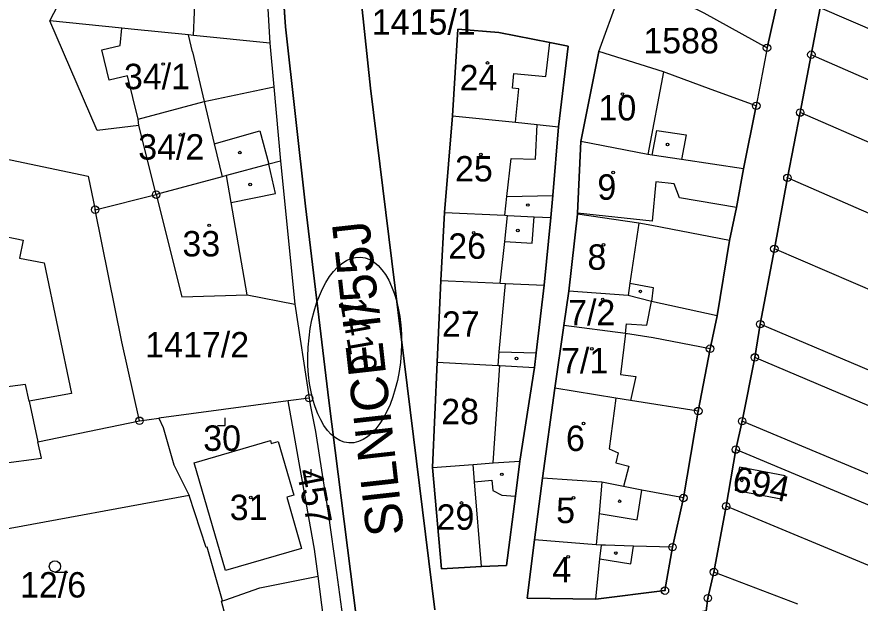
# Model space of a CAD drawing. Extents: x -537341 to -532984, y -1143469 to -1141314.
# Drawn here: x -534096.7 to -533983.8, y -1143219.6 to -1143141.1 of the extents above; entities that cross this region are included whole.
import ezdxf

# ---------------------------------------------------------------- set-up
doc = ezdxf.new("R2010")
doc.units = 0
for name, color, linetype in [('Hranice parcel', 7, 'Continuous'), ('parcelní_č_2000', 7, 'Continuous'), ('u_II_etapa', 7, 'Continuous'), ('u_obec_Horní_Moš', 7, 'Continuous'), ('u_popis', 7, 'Continuous'), ('u_ŘSD', 7, 'Continuous'), ('Vnitřní kresba', 7, 'Continuous'), ('Značky bodu BP', 7, 'Continuous'), ('Značky budov', 7, 'Continuous'), ('Značky kultur', 7, 'Continuous')]:
    doc.layers.add(name, color=color, linetype=linetype)

msp = doc.modelspace()

# ---------------------------------------------------------------- linework, layer by layer
at = {"layer": 'Hranice parcel'}
for p, q in [((-534063.52, -1143132.72), (-534062.89, -1143144.66)), ((-534018.84, -1143145.76), (-534015.29, -1143136.02)), ((-533996.31, -1143145.28), (-533994.84, -1143138.68)), ((-533989.18, -1143139.91), (-533990.38, -1143146.19)), ((-533940.79, -1143160.96), (-533989.18, -1143139.91)), ((-534062.89, -1143144.66), (-534073.09, -1143143.62)), ((-534062.89, -1143144.66), (-534062.35, -1143150.49)), ((-533996.31, -1143145.28), (-533997.75, -1143153.04)), ((-534018.84, -1143145.76), (-534021.24, -1143157.82)), ((-533990.38, -1143146.19), (-533991.87, -1143153.94)), ((-533941.88, -1143167.54), (-533990.38, -1143146.19)), ((-534062.35, -1143150.49), (-534061.42, -1143160.46)), ((-533999.48, -1143161.48), (-533997.75, -1143153.04)), ((-534038.43, -1143154.37), (-534039.5, -1143167.31)), ((-533991.87, -1143153.94), (-533993.58, -1143162.67)), ((-533941.49, -1143175.82), (-533991.87, -1143153.94)), ((-534078.08, -1143164.92), (-534080.41, -1143155.65)), ((-534021.24, -1143157.82), (-534021.67, -1143167.42)), ((-534061.42, -1143160.46), (-534059.51, -1143179.59)), ((-534000.41, -1143166.64), (-533999.48, -1143161.48)), ((-533993.58, -1143162.67), (-533995.33, -1143172.18)), ((-533941.43, -1143185.4), (-533993.58, -1143162.67)), ((-534086.26, -1143166.94), (-534078.08, -1143164.92)), ((-534001.33, -1143171.07), (-534000.41, -1143166.64)), ((-534039.5, -1143167.31), (-534039.98, -1143176.39)), ((-534026.15, -1143177.04), (-534025.25, -1143167.98)), ((-534021.68, -1143167.55), (-534022.84, -1143177.84)), ((-534021.67, -1143167.42), (-534021.68, -1143167.55)), ((-534002.98, -1143181.15), (-534001.33, -1143171.07)), ((-533995.33, -1143172.18), (-533997.21, -1143182.26)), ((-533938.53, -1143196.64), (-533995.33, -1143172.18)), ((-534039.98, -1143176.39), (-534040.45, -1143187.32)), ((-534022.84, -1143177.84), (-534023.53, -1143182.45)), ((-534059.51, -1143179.59), (-534057.6, -1143192.16)), ((-534003.94, -1143185.54), (-534002.98, -1143181.15)), ((-534023.53, -1143182.45), (-534024.73, -1143190.82)), ((-533997.21, -1143182.26), (-533997.94, -1143186.7)), ((-533912.37, -1143218.25), (-533997.21, -1143182.26)), ((-534005.51, -1143193.89), (-534003.94, -1143185.54)), ((-534040.45, -1143187.32), (-534041.08, -1143201.42)), ((-533997.94, -1143186.7), (-533999.64, -1143195.24)), ((-533899.82, -1143228.49), (-533997.94, -1143186.7)), ((-534029.39, -1143200.57), (-534027.43, -1143188.07)), ((-534024.73, -1143190.82), (-534026.35, -1143202.87)), ((-534060.41, -1143192.53), (-534077.71, -1143194.83)), ((-534057.6, -1143192.16), (-534060.41, -1143192.53)), ((-534007.5, -1143205.52), (-534005.51, -1143193.89)), ((-534080.32, -1143195.18), (-534077.71, -1143194.83)), ((-533999.64, -1143195.24), (-534000.48, -1143199.04)), ((-533879.1, -1143245.67), (-533999.64, -1143195.24)), ((-534000.48, -1143199.04), (-534001.78, -1143206.62)), ((-533869.5, -1143253.89), (-534000.48, -1143199.04)), ((-534026.35, -1143202.87), (-534027.42, -1143211.12)), ((-534073.67, -1143205.2), (-534107.09, -1143211.31)), ((-534008.96, -1143212.1), (-534007.5, -1143205.52)), ((-534001.78, -1143206.62), (-534003.42, -1143215.43)), ((-533862.31, -1143264.57), (-534001.78, -1143206.62)), ((-533992.17, -1143219.75), (-534003.42, -1143215.43)), ((-534055.69, -1143221.58), (-534056.42, -1143215.99))]:
    msp.add_line(p, q, dxfattribs=at)
for points in [[(-534061.91, -1143087.65), (-534062.34, -1143105.07), (-534062.29, -1143115.63), (-534061.93, -1143125.74), (-534060.79, -1143142.46), (-534058.08, -1143166.45), (-534054.98, -1143192.46), (-534048.78, -1143241.39), (-534046.39, -1143261.54)], [(-534040.76, -1143220.49), (-534049.39, -1143150.66), (-534051, -1143135.44), (-534051.84, -1143114.55)], [(-534092.32, -1143141.66), (-534090.18, -1143137.52), (-534086.71, -1143130.95), (-534079.93, -1143118.06)], [(-534073.09, -1143143.62), (-534072.57, -1143131.1), (-534071.45, -1143128.84)], [(-534015.29, -1143136.02), (-534006.96, -1143139.52), (-534004.77, -1143140.6), (-533996.31, -1143145.28)], [(-534073.09, -1143143.62), (-534073.76, -1143143.55), (-534081.43, -1143142.77), (-534082.69, -1143142.64), (-534092.32, -1143141.66)], [(-534080.41, -1143155.65), (-534086, -1143156.32), (-534092.32, -1143141.66)], [(-534024.21, -1143155.84), (-534022.92, -1143145.03), (-534025.38, -1143144.58), (-534032.22, -1143143.24), (-534037.69, -1143142.76), (-534038.43, -1143154.37)], [(-533997.75, -1143153.04), (-534003.77, -1143150.87), (-534010.17, -1143148.48), (-534018.84, -1143145.76)], [(-534080.41, -1143155.65), (-534080.51, -1143154.83), (-534071.65, -1143152.45), (-534062.35, -1143150.49)], [(-534038.43, -1143154.37), (-534029.96, -1143155.24), (-534027.07, -1143155.54), (-534024.21, -1143155.84)], [(-534113.97, -1143156.81), (-534087.18, -1143162.45), (-534086.26, -1143166.94)], [(-534025.25, -1143167.98), (-534025, -1143165.03), (-534024.21, -1143155.84)], [(-533999.48, -1143161.48), (-534007.76, -1143160.2), (-534011.68, -1143159.64), (-534012.28, -1143159.55), (-534021.24, -1143157.82)], [(-534061.42, -1143160.46), (-534062.99, -1143160.84), (-534068.67, -1143162.38), (-534069.26, -1143162.54), (-534078.08, -1143164.92)], [(-534078.08, -1143164.92), (-534074.66, -1143178.62), (-534065.92, -1143178.32), (-534059.51, -1143179.59)], [(-534080.32, -1143195.18), (-534082.67, -1143184.62), (-534086.26, -1143166.94)], [(-534039.5, -1143167.31), (-534031.39, -1143167.69), (-534031.05, -1143167.71), (-534027.48, -1143167.88), (-534025.25, -1143167.98)], [(-534001.33, -1143171.07), (-534011.71, -1143169.07), (-534013.46, -1143168.73), (-534021.68, -1143167.55)], [(-534039.98, -1143176.39), (-534032.04, -1143176.76), (-534031.34, -1143176.8), (-534026.15, -1143177.04)], [(-534027.43, -1143188.07), (-534027.2, -1143186.08), (-534026.15, -1143177.04)], [(-534002.98, -1143181.15), (-534011.76, -1143179.24), (-534014.91, -1143178.42), (-534022.84, -1143177.84)], [(-534003.94, -1143185.54), (-534011.53, -1143184.08), (-534015.26, -1143183.49), (-534023.53, -1143182.45)], [(-534040.45, -1143187.32), (-534032.32, -1143187.79), (-534032.07, -1143187.8), (-534027.43, -1143188.07)], [(-534005.51, -1143193.89), (-534014.59, -1143192.49), (-534016.56, -1143192.16), (-534024.73, -1143190.82)], [(-534117.77, -1143193.13), (-534105.37, -1143192.05), (-534104.3, -1143201.62), (-534093.45, -1143200.21), (-534093.95, -1143198.01), (-534080.32, -1143195.18)], [(-534056.42, -1143215.99), (-534056.89, -1143212.39), (-534057.64, -1143208.15), (-534059.61, -1143197.01), (-534060.41, -1143192.53)], [(-534057.6, -1143192.16), (-534057.46, -1143193.07), (-534056.77, -1143196.62), (-534055.08, -1143207.53), (-534053.95, -1143215.5), (-534053.13, -1143221.37)], [(-534077.71, -1143194.83), (-534077.14, -1143196.1), (-534075.7, -1143201.08), (-534073.67, -1143205.2)], [(-534059.67, -1143205.16), (-534060.6, -1143205.41), (-534058.64, -1143212.28), (-534068.82, -1143215.22), (-534072.99, -1143200.81), (-534062.78, -1143197.81), (-534062.67, -1143198.23), (-534061.74, -1143197.98), (-534059.67, -1143205.16)], [(-534041.08, -1143201.42), (-534035.64, -1143201.02), (-534032.99, -1143200.83), (-534029.39, -1143200.57)], [(-534041.08, -1143201.42), (-534039.89, -1143215.01), (-534034.52, -1143214.7), (-534031.2, -1143214.56), (-534029.99, -1143205.29), (-534029.39, -1143200.57)], [(-533994.42, -1143205.62), (-533993.88, -1143202.57), (-534000, -1143201.41), (-534000.57, -1143204.45), (-533994.42, -1143205.62)], [(-534007.5, -1143205.52), (-534013.05, -1143204.45), (-534015.52, -1143203.97), (-534018.43, -1143203.41), (-534026.35, -1143202.87)], [(-534069.19, -1143219.29), (-534071.26, -1143212.1), (-534071.41, -1143212.14), (-534073.67, -1143205.2)], [(-534027.42, -1143211.12), (-534028.44, -1143218.92), (-534019.21, -1143219.08), (-534009.98, -1143217.92), (-534008.96, -1143212.1)], [(-534008.96, -1143212.1), (-534014.17, -1143211.95), (-534017.95, -1143211.85), (-534018.49, -1143211.83), (-534019.19, -1143211.81), (-534027.42, -1143211.12)], [(-534003.42, -1143215.43), (-534004.23, -1143218.93), (-534004.45, -1143220.61), (-534008.52, -1143221.33), (-534023.43, -1143221.73), (-534023.59, -1143233.75)], [(-534069.19, -1143219.29), (-534068.9, -1143219.21), (-534064.19, -1143217.54), (-534056.42, -1143215.99)], [(-534070.76, -1143223.04), (-534068.43, -1143222.69), (-534069.33, -1143219.33), (-534069.19, -1143219.29)]]:
    msp.add_lwpolyline(points, dxfattribs=at)
at = {"layer": 'u_II_etapa'}
msp.add_ellipse((-534051.51, -1143185.72), major_axis=(-0.77, -12.43), ratio=0.50074, dxfattribs=at)
msp.add_ellipse((-534051.51, -1143185.72), major_axis=(-0.77, -12.43), ratio=0.50074, dxfattribs=at)
at = {"layer": 'u_obec_Horní_Moš'}
for p, q in [((-534063.52, -1143132.72), (-534062.89, -1143144.66)), ((-534018.84, -1143145.76), (-534015.29, -1143136.02)), ((-533994.84, -1143138.68), (-533996.31, -1143145.28)), ((-533990.38, -1143146.19), (-533989.18, -1143139.91)), ((-534058.08, -1143166.45), (-534060.79, -1143142.46)), ((-534062.89, -1143144.66), (-534062.35, -1143150.49)), ((-533996.31, -1143145.28), (-533997.75, -1143153.04)), ((-534021.24, -1143157.82), (-534018.84, -1143145.76)), ((-533991.87, -1143153.94), (-533990.38, -1143146.19)), ((-534062.35, -1143150.49), (-534061.42, -1143160.46)), ((-533997.75, -1143153.04), (-533999.48, -1143161.48)), ((-534039.5, -1143167.31), (-534038.43, -1143154.37)), ((-533993.58, -1143162.67), (-533991.87, -1143153.94)), ((-534078.08, -1143164.92), (-534080.41, -1143155.65)), ((-534021.67, -1143167.42), (-534021.24, -1143157.82)), ((-534061.42, -1143160.46), (-534059.51, -1143179.59)), ((-533999.48, -1143161.48), (-534000.41, -1143166.64)), ((-533995.33, -1143172.18), (-533993.58, -1143162.67)), ((-534086.26, -1143166.94), (-534078.08, -1143164.92)), ((-534000.41, -1143166.64), (-534001.33, -1143171.07)), ((-534039.98, -1143176.39), (-534039.5, -1143167.31)), ((-534025.25, -1143167.98), (-534026.15, -1143177.04)), ((-534022.84, -1143177.84), (-534021.68, -1143167.55)), ((-534021.68, -1143167.55), (-534021.67, -1143167.42)), ((-534001.33, -1143171.07), (-534002.98, -1143181.15)), ((-533997.21, -1143182.26), (-533995.33, -1143172.18)), ((-534040.45, -1143187.32), (-534039.98, -1143176.39)), ((-534023.53, -1143182.45), (-534022.84, -1143177.84)), ((-534059.51, -1143179.59), (-534057.6, -1143192.16)), ((-534002.98, -1143181.15), (-534003.94, -1143185.54)), ((-534024.73, -1143190.82), (-534023.53, -1143182.45)), ((-533997.94, -1143186.7), (-533997.21, -1143182.26)), ((-534003.94, -1143185.54), (-534005.51, -1143193.89)), ((-534041.08, -1143201.42), (-534040.45, -1143187.32)), ((-533999.64, -1143195.24), (-533997.94, -1143186.7)), ((-534027.43, -1143188.07), (-534029.39, -1143200.57)), ((-534026.35, -1143202.87), (-534024.73, -1143190.82)), ((-534005.51, -1143193.89), (-534007.5, -1143205.52)), ((-534000.48, -1143199.04), (-533999.64, -1143195.24)), ((-534001.78, -1143206.62), (-534000.48, -1143199.04)), ((-534029.39, -1143200.57), (-534029.99, -1143205.29)), ((-534027.42, -1143211.12), (-534026.35, -1143202.87)), ((-534007.5, -1143205.52), (-534008.96, -1143212.1)), ((-534003.42, -1143215.43), (-534001.78, -1143206.62))]:
    msp.add_line(p, q, dxfattribs=at)
for points in [[(-534051.84, -1143114.55), (-534051, -1143135.44), (-534049.39, -1143150.66), (-534040.76, -1143220.49)], [(-534060.79, -1143142.46), (-534061.93, -1143125.74), (-534062.29, -1143115.63)], [(-534092.32, -1143141.66), (-534090.18, -1143137.52), (-534086.71, -1143130.95), (-534079.93, -1143118.06)], [(-534080.41, -1143155.65), (-534086, -1143156.32), (-534092.32, -1143141.66)], [(-534038.43, -1143154.37), (-534037.69, -1143142.76), (-534032.22, -1143143.24), (-534025.38, -1143144.58), (-534022.92, -1143145.03), (-534024.21, -1143155.84)], [(-534113.97, -1143156.81), (-534087.18, -1143162.45), (-534086.26, -1143166.94)], [(-534024.21, -1143155.84), (-534025, -1143165.03), (-534025.25, -1143167.98)], [(-534048.78, -1143241.39), (-534054.98, -1143192.46), (-534058.08, -1143166.45)], [(-534026.15, -1143177.04), (-534027.2, -1143186.08), (-534027.43, -1143188.07)], [(-534057.6, -1143192.16), (-534057.46, -1143193.07), (-534056.77, -1143196.62), (-534055.08, -1143207.53), (-534053.95, -1143215.5), (-534053.13, -1143221.37)], [(-534029.99, -1143205.29), (-534031.2, -1143214.56), (-534034.52, -1143214.7), (-534039.89, -1143215.01), (-534041.08, -1143201.42)], [(-534008.96, -1143212.1), (-534009.98, -1143217.92), (-534019.21, -1143219.08), (-534028.44, -1143218.92), (-534027.42, -1143211.12)], [(-534023.59, -1143233.75), (-534023.43, -1143221.73), (-534008.52, -1143221.33), (-534004.45, -1143220.61), (-534004.23, -1143218.93), (-534003.42, -1143215.43)]]:
    msp.add_lwpolyline(points, dxfattribs=at)
at = {"layer": 'u_ŘSD'}
for p, q in [((-534061.93, -1143125.74), (-534060.79, -1143142.46)), ((-534060.79, -1143142.46), (-534058.08, -1143166.45)), ((-534058.08, -1143166.45), (-534054.98, -1143192.46)), ((-534054.98, -1143192.46), (-534048.78, -1143241.39))]:
    msp.add_line(p, q, dxfattribs=at)
msp.add_lwpolyline([(-534040.76, -1143220.49), (-534049.39, -1143150.66), (-534051, -1143135.44), (-534051.84, -1143114.55)], dxfattribs=at)
at = {"layer": 'Vnitřní kresba'}
for p, q in [((-534082.9, -1143144.95), (-534082.69, -1143142.64)), ((-534073.22, -1143145.81), (-534073.76, -1143143.55)), ((-534085.37, -1143145.54), (-534082.9, -1143144.95)), ((-534084.38, -1143149.62), (-534085.37, -1143145.54)), ((-534025.93, -1143149.09), (-534025.38, -1143144.58)), ((-534073.22, -1143145.81), (-534071.65, -1143152.45)), ((-534030.39, -1143150.67), (-534030.2, -1143148.69)), ((-534030.2, -1143148.69), (-534025.93, -1143149.09)), ((-534010.17, -1143148.48), (-534012.28, -1143159.55)), ((-534081.91, -1143149.02), (-534084.38, -1143149.62)), ((-534080.51, -1143154.83), (-534081.91, -1143149.02)), ((-534029.54, -1143150.75), (-534030.39, -1143150.67)), ((-534029.96, -1143155.24), (-534029.54, -1143150.75)), ((-534071.65, -1143152.45), (-534070.3, -1143158.14)), ((-534027.32, -1143160.17), (-534027.07, -1143155.54)), ((-534070.3, -1143158.14), (-534064.2, -1143156.38)), ((-534064.2, -1143156.38), (-534062.99, -1143160.84)), ((-534011.68, -1143159.64), (-534011.06, -1143156.35)), ((-534011.06, -1143156.35), (-534007.12, -1143156.92)), ((-534007.12, -1143156.92), (-534007.76, -1143160.2)), ((-534070.3, -1143158.14), (-534069.26, -1143162.54)), ((-534031.12, -1143165.16), (-534030.58, -1143160.09)), ((-534030.58, -1143160.09), (-534027.32, -1143160.17)), ((-534062.09, -1143164.76), (-534062.99, -1143160.84)), ((-534068.05, -1143165.98), (-534068.67, -1143162.38)), ((-534011.18, -1143163.21), (-534011.69, -1143168.48)), ((-534008.75, -1143163.46), (-534011.18, -1143163.21)), ((-534008.03, -1143165.33), (-534008.75, -1143163.46)), ((-534068.05, -1143165.98), (-534062.09, -1143164.76)), ((-534031.39, -1143167.69), (-534031.12, -1143165.16)), ((-534031.12, -1143165.16), (-534025, -1143165.03)), ((-534000.41, -1143166.64), (-534008.03, -1143165.33)), ((-534065.92, -1143178.32), (-534068.05, -1143165.98)), ((-534031.43, -1143171.19), (-534031.05, -1143167.71)), ((-534027.76, -1143171.42), (-534027.48, -1143167.88)), ((-534011.69, -1143168.48), (-534021.67, -1143167.42)), ((-534106.28, -1143168.85), (-534095.91, -1143171)), ((-534013.46, -1143168.73), (-534014.66, -1143176.75)), ((-534095.91, -1143171), (-534096.4, -1143173.42)), ((-534032.04, -1143176.76), (-534031.43, -1143171.19)), ((-534031.43, -1143171.19), (-534027.76, -1143171.42)), ((-534096.4, -1143173.42), (-534093.09, -1143174.05)), ((-534093.09, -1143174.05), (-534089.44, -1143191.55)), ((-534032.16, -1143185.96), (-534031.34, -1143176.8)), ((-534014.66, -1143176.75), (-534014.91, -1143178.42)), ((-534014.66, -1143176.75), (-534011.53, -1143177.34)), ((-534011.53, -1143177.34), (-534011.76, -1143179.24)), ((-534012.39, -1143182.37), (-534011.76, -1143179.24)), ((-534015.26, -1143183.49), (-534015.1, -1143182.2)), ((-534015.1, -1143182.2), (-534012.39, -1143182.37)), ((-534015.26, -1143183.49), (-534015.91, -1143188.99)), ((-534032.32, -1143187.79), (-534032.16, -1143185.96)), ((-534032.16, -1143185.96), (-534027.2, -1143186.08)), ((-534032.99, -1143200.83), (-534032.07, -1143187.8)), ((-534015.91, -1143188.99), (-534013.88, -1143189.27)), ((-534013.88, -1143189.27), (-534014.59, -1143192.49)), ((-534095.57, -1143190.34), (-534105.42, -1143191.6)), ((-534095.1, -1143192.54), (-534095.57, -1143190.34)), ((-534089.44, -1143191.55), (-534095.1, -1143192.54)), ((-534095.1, -1143192.54), (-534093.95, -1143198.01)), ((-534016.56, -1143192.16), (-534017.46, -1143198.95)), ((-534017.46, -1143198.95), (-534016.22, -1143199.48)), ((-534016.22, -1143199.48), (-534016.56, -1143200.83)), ((-534016.56, -1143200.83), (-534014.83, -1143201.28)), ((-534035.45, -1143203.36), (-534035.64, -1143201.02)), ((-534014.83, -1143201.28), (-534015.52, -1143203.97)), ((-534035.45, -1143203.36), (-534033.14, -1143203.15)), ((-534033.14, -1143203.15), (-534033.02, -1143204.53)), ((-534034.52, -1143214.7), (-534035.45, -1143203.36)), ((-534018.43, -1143203.41), (-534018.77, -1143207.59)), ((-534033.02, -1143204.53), (-534031.79, -1143205.12)), ((-534031.79, -1143205.12), (-534029.99, -1143205.29)), ((-534013.7, -1143208.46), (-534013.05, -1143204.45)), ((-534018.77, -1143207.59), (-534019.19, -1143211.81)), ((-534018.77, -1143207.59), (-534013.7, -1143208.46)), ((-534018.67, -1143213.66), (-534018.49, -1143211.83)), ((-534014.56, -1143214.34), (-534014.17, -1143211.95)), ((-534019.21, -1143219.08), (-534018.67, -1143213.66)), ((-534018.67, -1143213.66), (-534014.56, -1143214.34))]:
    msp.add_line(p, q, dxfattribs=at)
at = {"layer": 'Značky bodu BP'}
for centre, radius in [((-533996.31, -1143145.28), 0.5), ((-533996.31, -1143145.28), 0.0303), ((-533990.38, -1143146.19), 0.5), ((-533990.38, -1143146.19), 0.0303), ((-533997.75, -1143153.04), 0.5), ((-533997.75, -1143153.04), 0.0303), ((-533991.87, -1143153.94), 0.5), ((-533991.87, -1143153.94), 0.0303), ((-533993.58, -1143162.67), 0.5), ((-533993.58, -1143162.67), 0.0303), ((-534078.08, -1143164.92), 0.5), ((-534078.08, -1143164.92), 0.0303), ((-534086.26, -1143166.94), 0.5), ((-534086.26, -1143166.94), 0.0303), ((-533995.33, -1143172.18), 0.5), ((-533995.33, -1143172.18), 0.0303), ((-533997.21, -1143182.26), 0.5), ((-533997.21, -1143182.26), 0.0303), ((-534003.94, -1143185.54), 0.5), ((-534003.94, -1143185.54), 0.0303), ((-533997.94, -1143186.7), 0.5), ((-533997.94, -1143186.7), 0.0303), ((-534057.6, -1143192.16), 0.5), ((-534057.6, -1143192.16), 0.0303), ((-534005.51, -1143193.89), 0.5), ((-534005.51, -1143193.89), 0.0303), ((-534080.32, -1143195.18), 0.5), ((-534080.32, -1143195.18), 0.0303), ((-533999.64, -1143195.24), 0.5), ((-533999.64, -1143195.24), 0.0303), ((-534000.48, -1143199.04), 0.5), ((-534000.48, -1143199.04), 0.0303), ((-534007.5, -1143205.52), 0.5), ((-534007.5, -1143205.52), 0.0303), ((-534001.78, -1143206.62), 0.5), ((-534001.78, -1143206.62), 0.0303), ((-534008.96, -1143212.1), 0.5), ((-534008.96, -1143212.1), 0.0303), ((-534003.42, -1143215.43), 0.5), ((-534003.42, -1143215.43), 0.0303), ((-534009.98, -1143217.92), 0.5), ((-534009.98, -1143217.92), 0.0303), ((-534004.23, -1143218.93), 0.5), ((-534004.23, -1143218.93), 0.0303)]:
    msp.add_circle(centre, radius, dxfattribs=at)
at = {"layer": 'Značky budov'}
for centre in [(-534077.16, -1143147.44), (-534033.73, -1143147.3), (-534015.67, -1143151.46), (-534074.83, -1143156.93), (-534066.88, -1143159.3), (-534009.62, -1143158.2), (-534034.61, -1143159.54), (-534016.9, -1143161.95), (-534065.51, -1143163.56), (-534028.33, -1143166.31), (-534070.99, -1143169.03), (-534035.58, -1143170.03), (-534029.67, -1143169.72), (-534018.21, -1143171.64), (-534013.27, -1143177.87), (-534018.31, -1143178.93), (-534036.19, -1143180.66), (-534019.76, -1143185.55), (-534029.84, -1143186.86), (-534036.42, -1143192.29), (-534020.86, -1143195.55), (-534031.8, -1143202.35), (-533999.7, -1143203.16), (-534065.43, -1143205.46), (-534022.2, -1143205.51), (-534037.2, -1143206.18), (-534016.04, -1143205.96), (-534022.92, -1143213.39), (-534016.56, -1143212.89)]:
    msp.add_circle(centre, 0.175, dxfattribs=at)
at = {"layer": 'Značky kultur'}
for p, q in [((-534068.86, -1143195.81), (-534068.86, -1143194.81)), ((-534069.86, -1143195.81), (-534068.86, -1143195.81)), ((-534057.32, -1143202.66), (-534057.32, -1143201.66)), ((-534058.32, -1143202.66), (-534057.32, -1143202.66)), ((-534091.65, -1143215.43), (-534089.9, -1143215.43))]:
    msp.add_line(p, q, dxfattribs=at)
msp.add_circle((-534091.65, -1143214.68), 0.75, dxfattribs=at)

# ---------------------------------------------------------------- texts
at = {"layer": 'parcelní_č_2000'}
for s, p in [('1415/1', (-534049.22, -1143143.51)), ('1588', (-534012.87, -1143146.01)), ('34/1', (-534082.4, -1143150.81)), ('24', (-534037.47, -1143150.97)), ('10', (-534018.87, -1143154.99)), ('34/2', (-534080.49, -1143160.23)), ('25', (-534038.08, -1143163.16)), ('9', (-534019.02, -1143165.6)), ('33', (-534074.57, -1143173.19)), ('26', (-534038.98, -1143173.51)), ('8', (-534020.35, -1143174.98)), ('7/2', (-534022.94, -1143182.4)), ('27', (-534039.83, -1143183.94)), ('1417/2', (-534079.55, -1143186.71)), ('7/1', (-534023.89, -1143188.84)), ('28', (-534039.93, -1143195.65)), ('30', (-534071.79, -1143199.21)), ('6', (-534023.23, -1143199.23)), ('31', (-534068.24, -1143208.48)), ('29', (-534040.55, -1143209.77)), ('5', (-534024.54, -1143208.88)), ('4', (-534025.05, -1143216.81)), ('12/6', (-534096.31, -1143218.84))]:
    msp.add_text(s, height=3.4, dxfattribs=at).set_placement(p)
for s, rotation, p in [('1416', 280, (-534053.51, -1143179.07)), ('457', 281, (-534059.29, -1143201.89)), ('694', 348, (-534001.13, -1143204.53))]:
    msp.add_text(s, height=3.4, rotation=rotation, dxfattribs=at).set_placement(p)
at = {"layer": 'u_popis'}
msp.add_text('SILNICE I/55J', height=5, rotation=96.3761, dxfattribs=at).set_placement((-534044.9, -1143210.34))

doc.saveas('drawing.dxf')
